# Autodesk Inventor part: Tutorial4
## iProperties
Shininess: 64.0
Length Units: 11269
Angle Units: 11279
Time Units: 11290
Mass Units: 11283
Length Display Precision: 3
Angle Display Precision: 2
Compacted: True
Part Number: Tutorial4
Document SubType Name: Modeling
Created: 2002-11
Designer: deepak
Density: 0.0
Volumn: 0.0
Area: 0.0
PropertySet Name: Model Information
Control State: 0
Master: False
Checked Out: False
Author: deepak
